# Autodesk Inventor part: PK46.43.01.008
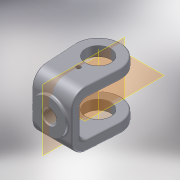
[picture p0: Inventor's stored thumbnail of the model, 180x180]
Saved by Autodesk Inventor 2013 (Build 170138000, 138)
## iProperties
Shininess: 64.0
Length Units: 11269
Angle Units: 11279
Time Units: 11290
Mass Units: 11283
Length Display Precision: 3
Angle Display Precision: 2
Compacted: True
Part Number: PK46.43.01.008
Document SubType Name: Modeling
Created: 2004-11
Material: Сталь высокопрочная низколегированная
Designer: ELarisa
Manufacturer: Standard
Standards Organization: Custom
Density: 7.84 g/cm^3
Density: 0.0
Volumn: 0.0
Area: 0.0
PropertySet Name: Model Information
Control State: 0
Master: False
Checked Out: False
Checked Out Date: 2008-10-09
Last Check In Date: 2008-10-09
Author: ELarisa
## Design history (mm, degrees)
sketch "Эскиз1"
  geometry: L1 (118.504, -3.432)-(118.504, -3.593); L2 (188.504, -10.209)-(48.504, -10.209); L3 (48.504, -10.209)-(38.655, 149.878); L4 (188.504, -10.209)-(198.353, 149.878); A1 r 80 centre (118.504, 154.791) between (198.353, 149.878) and (38.655, 149.878)
  constraints: 8 end point, 2 point on circle, 2 symmetric about line, 1 centre point, 1 perpendicular, 1 tangent, 1 other
  dimensions: "d0" = 80 radius of A1; "d1" = 140 distance of L2.start L2.end; "d2" = 165 distance from line of L2 A1.centre
extrude "Выдавливание1" new body sketch "Эскиз1" distance "d3" = 200; taper "d4" = 0 deg
workaxis "Work Axis1"
fillet "Сопряжение1" dims "d5" = 50
workplane "Work Plane3"
sketch "Эскиз2"
  geometry: L1 (35, 130)-(165, 130); L2 (165, 130)-(165, -150); L3 (165, -150)-(35, -150); L4 (35, -150)-(35, 130); L5 (0, -19.512)-(0, 70); L6 (-40, 0)-(240, 0) reference; L7 (50, 165)-(150, 165) reference; L8 (200, 4.913)-(200, 115) reference; L9 (0, 115)-(0, 4.913) reference
  constraints: 10 end point, 2 parallel, 1 collinear, 1 horizontal, 1 perpendicular
  dimensions: "d7" = 35 distance between parallel lines of L4 L5; "d42" = 35 distance between parallel lines of L7 L1; "d43" = 280 distance of L3.end L1.start; "d66" = 35 distance between parallel lines of L8 L2 (= d7)
extrude "Выдавливание2" cut sketch "Эскиз2" stored distance "d10" = 200; taper "d11" = 0 deg
node "РабПлоскость1"
sketch "Эскиз5"
  geometry: L1 (0, 0)-(0, 100) reference; L2 (143.076, 150)-(-3.076, 150) reference; C1 r 60 at (70, 50)
  constraints: 1 centre point
  dimensions: "d24" = 120 diameter of C1; "d25" = 100 distance from line of L2 C1.centre; "d26" = 70 distance from line of L1 C1.centre
extrude "Выдавливание4" join sketch "Эскиз5" distance "d27" = 10; taper "d28" = 0 deg
sketch "Sketch7"
  geometry: C1 r 60 at (0, 0) reference
hole "Hole3" sketch "Sketch7" at (0, 0) diameter "d46" = 49.835; stored, may be unused: countersink angle "d50" = 82 deg, drill point angle "d52" = 118 deg; dims "d47" = 6, "d48" = 56, "d49" = 2, "d51" = 8
fillet "Fillet4" dims "d53" = 20
sketch "Sketch8"
  geometry: A1 r 80 centre (-118.504, 154.791) between (-38.655, 149.878) and (-198.353, 149.878) reference
hole "Hole4" sketch "Sketch8" at (-118.504, 154.791) diameter "d54" = 90; stored, may be unused: countersink angle "d58" = 82 deg, drill point angle "d60" = 118 deg; dims "d55" = 6, "d56" = 68, "d57" = 2, "d59" = 8
sketch "Эскиз9"
  geometry: L1 (118.504, 283.791)-(118.504, -59.209) reference; C1 r 8 at (118.504, 84.791); 1 further point
  constraints: 1 centre point
  dimensions: "d61" = 0 distance from line of L1 C1.centre; "d62" = 70 distance of point (118.504, 154.791) C1.centre; "d63" = 16 diameter of C1
extrude "Выдавливание5" cut sketch "Эскиз9" stored distance "d64" = 10; taper "d65" = 0 deg
fillet "Сопряжение6" dims "d73" = 15, "d74" = 15, "d75" = 5, "d76" = 0, "d77" = 15, "d78" = 0, "d79" = 15, "d80" = 0, "d81" = 5, "d82" = 0, "d83" = 5, "d84" = 0, "d85" = 5, "d86" = 0, "d87" = 15, "d88" = 0, "d89" = 15, "d90" = 0, "d91" = 5, "d92" = 0, "d96" = 5, "d97" = 10
fillet "Сопряжение7" dims "d93" = 5
fillet "Сопряжение8" dims "d94" = 5
fillet "Сопряжение9" dims "d95" = 5
body "Solid1"
other parameters: "d41" = 90 deg
